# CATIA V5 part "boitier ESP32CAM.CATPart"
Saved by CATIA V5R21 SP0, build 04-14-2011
Part number: boitier ESP32CAM
Bounding box of the stored display mesh (mm): x -18.5 to 18.5, y -25 to 25, z 0 to 25
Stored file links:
  C:\Users\pc\Desktop\PFA SIMULATION\boitier ESP32CAM.CATPart
  C:\Users\pc\Desktop\PFA SIMULATION\ESP32CAM model.CATPart
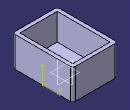
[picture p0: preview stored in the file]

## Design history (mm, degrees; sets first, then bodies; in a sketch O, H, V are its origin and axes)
Body1 (main body)
  Sketch1 on xy-plane, origin (0, 0, 0), H (1, 0, 0), V (0, 1, 0)
    line L1 (-18.5, 25) -> (18.5, 25)
    line L2 (18.5, 25) -> (18.5, -25)
    line L3 (18.5, -25) -> (-18.5, -25)
    line L4 (-18.5, -25) -> (-18.5, 25)
    distance L4 L2 = 37
    distance L4 V = 18.5
    distance L1 L3 = 50
    distance L3 H = 25
  Pad1: profile Sketch1, direction (0, 0, 1), length 25
  Sketch2 on end face of Pad1, origin (0, 0, 25), H (1, 0, 0), V (0, 1, 0)
    line L1 (-15.5, 22) -> (15.5, 22)
    line L2 (15.5, 22) -> (15.5, -22)
    line L3 (15.5, -22) -> (-15.5, -22)
    line L4 (-15.5, -22) -> (-15.5, 22)
    reference projected line E1 (16, 25) -> (-16, 25) from edge [face of Pad1 from Sketch1.L1 | end face of Pad1]
    reference projected line E2 (18.5, -20.5) -> (18.5, 24.5) from edge [face of Pad1 from Sketch1.L2 | end face of Pad1]
    reference projected line E3 (-18.5, 24.5) -> (-18.5, -20.5) from edge [face of Pad1 from Sketch1.L4 | end face of Pad1]
    reference projected line E4 (-16, -25) -> (16, -25) from edge [face of Pad1 from Sketch1.L3 | end face of Pad1]
    distance E1 L1 = 3
    distance L2 E2 = 3
    distance E3 L4 = 3
    distance L3 E4 = 3
  Pocket1: profile Sketch2, direction (0, 0, -1), length 22
  Fillet1: radius 2, on edge [face of Pad1 from Sketch1.L4 | face of Pad1 from Sketch1.L1]
  Fillet2: radius 2, on edge [face of Pad1 from Sketch1.L1 | face of Pad1 from Sketch1.L2]
  Fillet3: radius 2, on edge [face of Pad1 from Sketch1.L3 | face of Pad1 from Sketch1.L4]
  Fillet4: radius 2, on edge [face of Pad1 from Sketch1.L2 | face of Pad1 from Sketch1.L3]
  Sketch3 on end face of Pad1, origin (0, 0, 25), H (1, 0, 0), V (0, 1, 0)
    line L1 (-18.5, 25) -> (18.5, 25)
    line L2 (18.5, 25) -> (18.5, -25)
    line L3 (18.5, -25) -> (-18.5, -25)
    line L4 (-18.5, -25) -> (-18.5, 25)
    reference projected line E1 (18.5, 25) -> (-18.5, 25) from edge [face of Pad1 from Sketch1.L1 | end face of Pad1]
    reference projected line E2 (-18.5, -25) -> (18.5, -25) from edge [face of Pad1 from Sketch1.L3 | end face of Pad1]
    line L5 (-40, 40) -> (40, 40)
    line L6 (40, 40) -> (40, -40)
    line L7 (40, -40) -> (-40, -40)
    line L8 (-40, -40) -> (-40, 40)
    distance L1 E1 = 0
    distance L3 E2 = 0
  Pocket2: profile Sketch3, direction (0, 0, -1), length 5
  Fillet5: radius 2, on edge [face of Pocket2 from Sketch3.L1 | face of Pocket2 from Sketch3.L4]
  Fillet6: radius 2, on edge [face of Pocket2 from Sketch3.L2 | face of Pocket2 from Sketch3.L1]
  Fillet7: radius 2, on edge [face of Pocket2 from Sketch3.L4 | face of Pocket2 from Sketch3.L3]
  Fillet8: radius 2, on edge [face of Pocket2 from Sketch3.L3 | face of Pocket2 from Sketch3.L2]
  Sketch4 on face of Pad1 from Sketch1.L2, origin (18.5, 0, 0), H (0, 1, 0), V (0, 0, 1)
  Sketch5 on face of Pad1 from Sketch1.L3, origin (0, -25, 0), H (1, 0, 0), V (0, 0, 1)
    line L1 (-5, 10) -> (5, 10)
    line L2 (5, 10) -> (5, 5)
    line L3 (5, 5) -> (-5, 5)
    line L4 (-5, 5) -> (-5, 10)
    length L1 = 10
    distance L4 V = 5
    distance L3 H = 5
    length L2 = 5
    angle L1 L2 = 90
    angle L4 L1 = 90
  Pocket3: profile Sketch5, direction (0, 1, 0), length 10
  Sketch6 on end face of Pad1, origin (0, 0, 25), H (1, 0, 0), V (0, 1, 0)
  Pad2: profile Sketch6, direction (0, 0, 1), length 9
  Sketch7 on start face of Pad1, origin (0, 0, 0), H (1, 0, 0), V (0, 1, 0)
    line L1 (-18.5, 25) -> (18.5, 25)
    line L2 (18.5, 25) -> (18.5, -25)
    line L3 (18.5, -25) -> (-18.5, -25)
    line L4 (-18.5, -25) -> (-18.5, 25)
    distance L4 L2 = 37
    distance L4 V = 18.5
    distance L1 L3 = 50
    distance L3 H = 25
  Pad3: profile Sketch7, direction (0, 0, 1), length 25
